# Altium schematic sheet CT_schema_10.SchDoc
size 274 x 160 mm
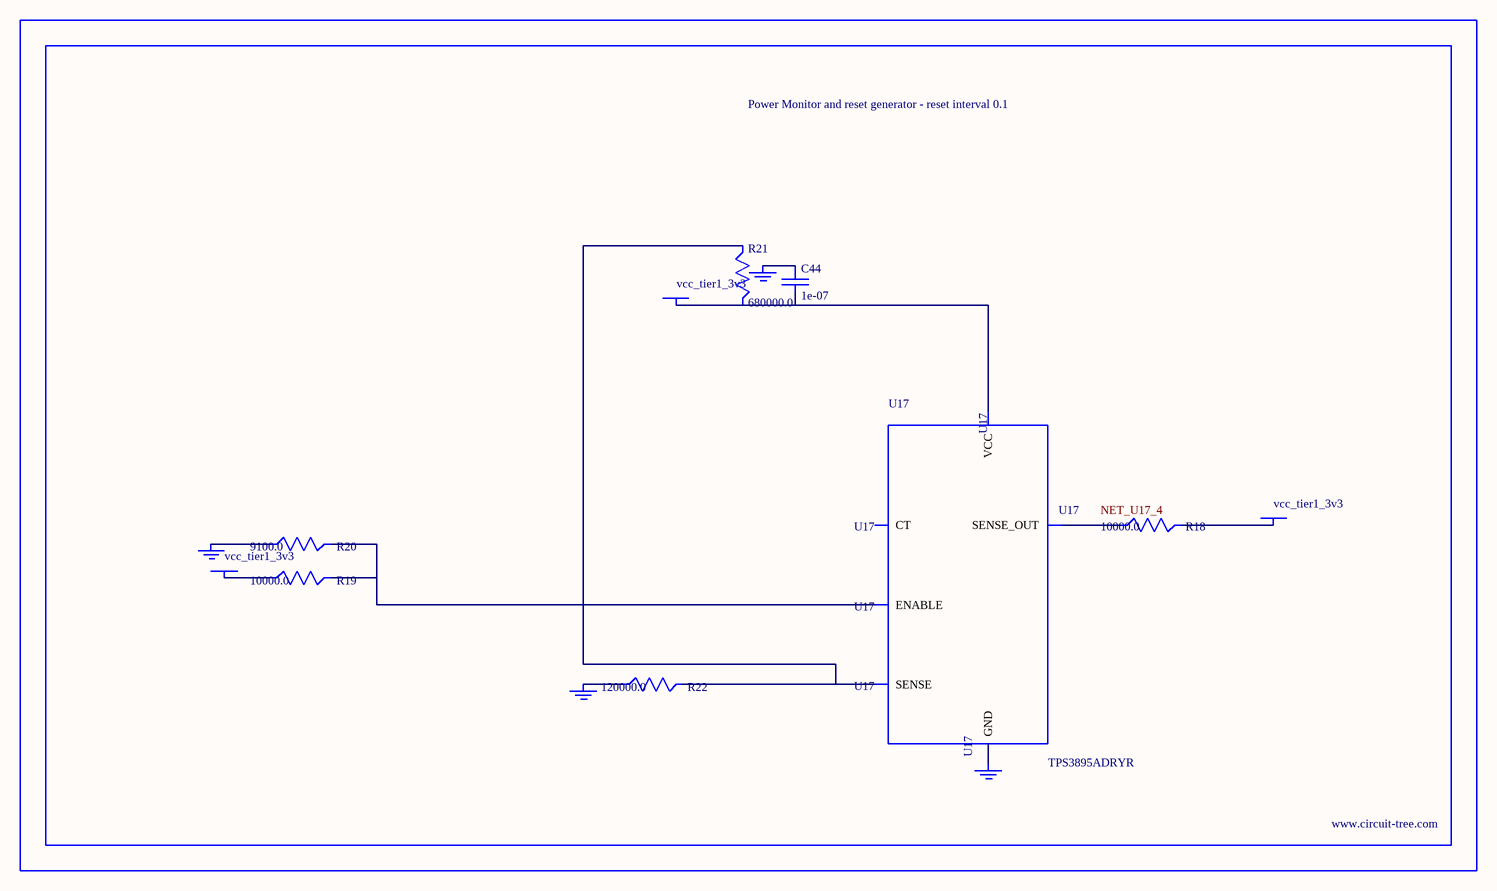
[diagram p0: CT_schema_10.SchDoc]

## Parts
BORDER9  (no value)
C44  1e-07  [C0402]
GND_INSTANCE_9_0  (no value)
GND_INSTANCE_9_1  (no value)
GND_INSTANCE_9_2  (no value)
GND_INSTANCE_9_3  (no value)
POWER_INSTANCE_9_0  vcc_tier1_3v3
POWER_INSTANCE_9_1  vcc_tier1_3v3
POWER_INSTANCE_9_2  vcc_tier1_3v3
R18  10000.0  [R0603]
R19  10000.0  [R0603]
R20  9100.0  [R0603]
R21  680000.0  [R0603]
R22  120000.0  [R0603]
U17  TPS3895ADRYR  [SON-6]

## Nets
NetC44_1: C44.1 GND_INSTANCE_9_2.0(GND)
NetC44_2: C44.2 POWER_INSTANCE_9_2.0(PWR) R21.2 U17.6(VCC)
NetGND_INSTANCE_9_0_0: GND_INSTANCE_9_0.0(GND) R20.1
NetGND_INSTANCE_9_1_0: GND_INSTANCE_9_1.0(GND) R22.1
NetGND_INSTANCE_9_3_0: GND_INSTANCE_9_3.0(GND) U17.2(GND)
NetPOWER_INSTANCE_9_0_0: POWER_INSTANCE_9_0.0(PWR) R19.1
NetPOWER_INSTANCE_9_1_0: POWER_INSTANCE_9_1.0(PWR) R18.2
NetR18_1: R18.1 U17.4(SENSE_OUT)
NetR19_2: R19.2 R20.2 U17.1(ENABLE)
NetR21_1: R21.1 R22.2 U17.3(SENSE)

Not connected (* = marked no-connect by the designer): U17 5(CT)

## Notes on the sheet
- Labels drawn without touching a wire or pin: NET_U17_4

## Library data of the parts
BORDER9 = BORDER_PAGE9
C44 = C0402C104K3RACTU
GND_INSTANCE_9_0-GND_INSTANCE_9_3 = GND
POWER_INSTANCE_9_0-POWER_INSTANCE_9_2 = PWR
R18 R19 = RC0603JR-0710KL
R20 = RC0603JR-079K1L
R21 = RC0603JR-07680KL
R22 = RC0603JR-07120KL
